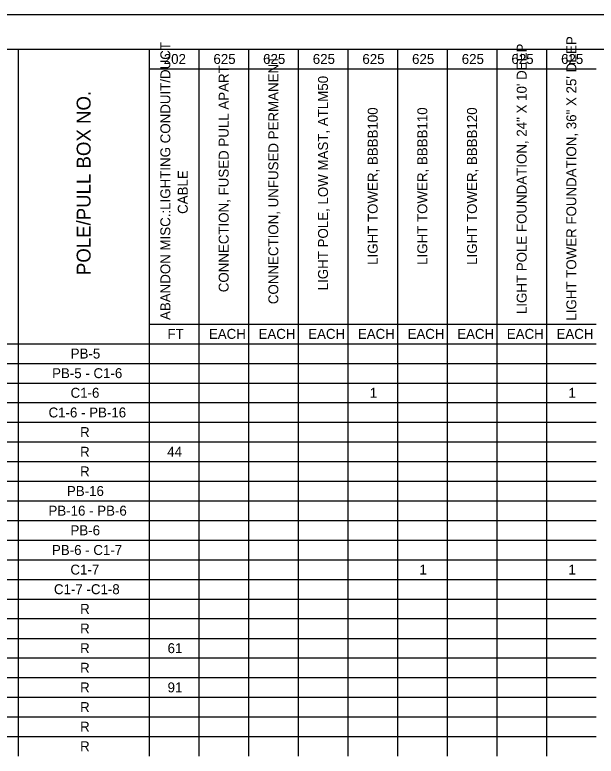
# Model space of a CAD drawing. Extents: x 0 to 34, y 0 to 22.
# Drawn here: x 8.35 to 16.82, y 11.19 to 22 of the extents above; entities that cross this region are included whole.
import ezdxf

# ---------------------------------------------------------------- set-up
doc = ezdxf.new("R2010")
doc.units = 0
for name, color, linetype in [('Default', 7, 'Continuous'), ('SH_Border', 7, 'Continuous'), ('SH_Cut_Line', 7, 'Continuous')]:
    doc.layers.add(name, color=color, linetype=linetype)

msp = doc.modelspace()

# ---------------------------------------------------------------- linework, layer by layer
at = {"layer": 'Default'}
for p, q in [((5.433, 21.5), (13.203, 21.5)), ((8.396, 21.5), (8.396, 21.214)), ((10.308, 21.5), (10.308, 21.214)), ((11.032, 21.5), (11.032, 21.214)), ((11.756, 21.5), (11.756, 21.214)), ((12.479, 21.5), (12.479, 21.214)), ((13.203, 21.5), (13.927, 21.5)), ((13.203, 21.5), (13.203, 21.214)), ((13.927, 21.5), (14.651, 21.5)), ((13.927, 21.5), (13.927, 21.214)), ((14.651, 21.5), (15.374, 21.5)), ((14.651, 21.5), (14.651, 21.214)), ((15.374, 21.5), (16.822, 21.5)), ((15.374, 21.5), (15.374, 21.214)), ((16.098, 21.5), (16.098, 21.214)), ((8.396, 21.214), (8.396, 20.927)), ((10.308, 21.214), (13.203, 21.214)), ((10.308, 21.214), (10.308, 20.927)), ((11.032, 21.214), (11.032, 20.927)), ((11.756, 21.214), (11.756, 20.927)), ((12.479, 21.214), (12.479, 20.927)), ((13.203, 21.214), (13.927, 21.214)), ((13.203, 21.214), (13.203, 20.927)), ((13.927, 21.214), (14.651, 21.214)), ((13.927, 21.214), (13.927, 20.927)), ((14.651, 21.214), (15.374, 21.214)), ((14.651, 21.214), (14.651, 20.927)), ((15.374, 21.214), (16.822, 21.214)), ((15.374, 21.214), (15.374, 20.927)), ((16.098, 21.214), (16.098, 20.927)), ((8.396, 20.927), (8.396, 20.641)), ((10.308, 20.927), (10.308, 20.641)), ((11.032, 20.927), (11.032, 20.641)), ((11.756, 20.927), (11.756, 20.641)), ((12.479, 20.927), (12.479, 20.641)), ((13.203, 20.927), (13.203, 20.641)), ((13.927, 20.927), (13.927, 20.641)), ((14.651, 20.927), (14.651, 20.641)), ((15.374, 20.927), (15.374, 20.641)), ((16.098, 20.927), (16.098, 20.641)), ((8.396, 20.641), (8.396, 20.354)), ((10.308, 20.641), (10.308, 20.354)), ((11.032, 20.641), (11.032, 20.354)), ((11.756, 20.641), (11.756, 20.354)), ((12.479, 20.641), (12.479, 20.354)), ((13.203, 20.641), (13.203, 20.354)), ((13.927, 20.641), (13.927, 20.354)), ((14.651, 20.641), (14.651, 20.354)), ((15.374, 20.641), (15.374, 20.354)), ((16.098, 20.641), (16.098, 20.354)), ((8.396, 20.354), (8.396, 20.068)), ((10.308, 20.354), (10.308, 20.068)), ((11.032, 20.354), (11.032, 20.068)), ((11.756, 20.354), (11.756, 20.068)), ((12.479, 20.354), (12.479, 20.068)), ((13.203, 20.354), (13.203, 20.068)), ((13.927, 20.354), (13.927, 20.068)), ((14.651, 20.354), (14.651, 20.068)), ((15.374, 20.354), (15.374, 20.068)), ((16.098, 20.354), (16.098, 20.068)), ((8.396, 20.068), (8.396, 19.782)), ((10.308, 20.068), (10.308, 19.782)), ((11.032, 20.068), (11.032, 19.782)), ((11.756, 20.068), (11.756, 19.782)), ((12.479, 20.068), (12.479, 19.782)), ((13.203, 20.068), (13.203, 19.782)), ((13.927, 20.068), (13.927, 19.782)), ((14.651, 20.068), (14.651, 19.782)), ((15.374, 20.068), (15.374, 19.782)), ((16.098, 20.068), (16.098, 19.782)), ((8.396, 19.782), (8.396, 19.495)), ((10.308, 19.782), (10.308, 19.495)), ((11.032, 19.782), (11.032, 19.495)), ((11.756, 19.782), (11.756, 19.495)), ((12.479, 19.782), (12.479, 19.495)), ((13.203, 19.782), (13.203, 19.495)), ((13.927, 19.782), (13.927, 19.495)), ((14.651, 19.782), (14.651, 19.495)), ((15.374, 19.782), (15.374, 19.495)), ((16.098, 19.782), (16.098, 19.495)), ((8.396, 19.495), (8.396, 19.209)), ((10.308, 19.495), (10.308, 19.209)), ((11.032, 19.495), (11.032, 19.209)), ((11.756, 19.495), (11.756, 19.209)), ((12.479, 19.495), (12.479, 19.209)), ((13.203, 19.495), (13.203, 19.209)), ((13.927, 19.495), (13.927, 19.209)), ((14.651, 19.495), (14.651, 19.209)), ((15.374, 19.495), (15.374, 19.209)), ((16.098, 19.495), (16.098, 19.209)), ((8.396, 19.209), (8.396, 18.922)), ((10.308, 19.209), (10.308, 18.922)), ((11.032, 19.209), (11.032, 18.922)), ((11.756, 19.209), (11.756, 18.922)), ((12.479, 19.209), (12.479, 18.922)), ((13.203, 19.209), (13.203, 18.922)), ((13.927, 19.209), (13.927, 18.922)), ((14.651, 19.209), (14.651, 18.922)), ((15.374, 19.209), (15.374, 18.922)), ((16.098, 19.209), (16.098, 18.922)), ((8.396, 18.922), (8.396, 18.636)), ((10.308, 18.922), (10.308, 18.636)), ((11.032, 18.922), (11.032, 18.636)), ((11.756, 18.922), (11.756, 18.636)), ((12.479, 18.922), (12.479, 18.636)), ((13.203, 18.922), (13.203, 18.636)), ((13.927, 18.922), (13.927, 18.636)), ((14.651, 18.922), (14.651, 18.636)), ((15.374, 18.922), (15.374, 18.636)), ((16.098, 18.922), (16.098, 18.636)), ((8.396, 18.636), (8.396, 18.35)), ((10.308, 18.636), (10.308, 18.35)), ((11.032, 18.636), (11.032, 18.35)), ((11.756, 18.636), (11.756, 18.35)), ((12.479, 18.636), (12.479, 18.35)), ((13.203, 18.636), (13.203, 18.35)), ((13.927, 18.636), (13.927, 18.35)), ((14.651, 18.636), (14.651, 18.35)), ((15.374, 18.636), (15.374, 18.35)), ((16.098, 18.636), (16.098, 18.35)), ((8.396, 18.35), (8.396, 18.063)), ((10.308, 18.35), (10.308, 18.063)), ((11.032, 18.35), (11.032, 18.063)), ((11.756, 18.35), (11.756, 18.063)), ((12.479, 18.35), (12.479, 18.063)), ((13.203, 18.35), (13.203, 18.063)), ((13.927, 18.35), (13.927, 18.063)), ((14.651, 18.35), (14.651, 18.063)), ((15.374, 18.35), (15.374, 18.063)), ((16.098, 18.35), (16.098, 18.063)), ((8.396, 18.063), (8.396, 17.777)), ((10.308, 18.063), (10.308, 17.777)), ((11.032, 18.063), (11.032, 17.777)), ((11.756, 18.063), (11.756, 17.777)), ((12.479, 18.063), (12.479, 17.777)), ((13.203, 18.063), (13.203, 17.777)), ((13.927, 18.063), (13.927, 17.777)), ((14.651, 18.063), (14.651, 17.777)), ((15.374, 18.063), (15.374, 17.777)), ((16.098, 18.063), (16.098, 17.777)), ((8.396, 17.777), (8.396, 17.49)), ((10.308, 17.777), (10.308, 17.49)), ((11.032, 17.777), (11.032, 17.49)), ((11.756, 17.777), (11.756, 17.49)), ((12.479, 17.777), (12.479, 17.49)), ((13.203, 17.777), (13.203, 17.49)), ((13.927, 17.777), (13.927, 17.49)), ((14.651, 17.777), (14.651, 17.49)), ((15.374, 17.777), (15.374, 17.49)), ((16.098, 17.777), (16.098, 17.49)), ((8.396, 17.49), (8.396, 17.204)), ((10.308, 17.49), (13.203, 17.49)), ((10.308, 17.49), (10.308, 17.204)), ((11.032, 17.49), (11.032, 17.204)), ((11.756, 17.49), (11.756, 17.204)), ((12.479, 17.49), (12.479, 17.204)), ((13.203, 17.49), (13.927, 17.49)), ((13.203, 17.49), (13.203, 17.204)), ((13.927, 17.49), (14.651, 17.49)), ((13.927, 17.49), (13.927, 17.204)), ((14.651, 17.49), (15.374, 17.49)), ((14.651, 17.49), (14.651, 17.204)), ((15.374, 17.49), (16.822, 17.49)), ((15.374, 17.49), (15.374, 17.204)), ((16.098, 17.49), (16.098, 17.204)), ((5.433, 17.204), (13.203, 17.204)), ((8.396, 17.204), (8.396, 16.918)), ((10.308, 17.204), (10.308, 16.918)), ((11.032, 17.204), (11.032, 16.918)), ((11.756, 17.204), (11.756, 16.918)), ((12.479, 17.204), (12.479, 16.918)), ((13.203, 17.204), (13.927, 17.204)), ((13.203, 17.204), (13.203, 16.918)), ((13.927, 17.204), (14.651, 17.204)), ((13.927, 17.204), (13.927, 16.918)), ((14.651, 17.204), (15.374, 17.204)), ((14.651, 17.204), (14.651, 16.918)), ((15.374, 17.204), (16.822, 17.204)), ((15.374, 17.204), (15.374, 16.918)), ((16.098, 17.204), (16.098, 16.918)), ((5.433, 16.918), (13.203, 16.918)), ((8.396, 16.918), (8.396, 16.631)), ((10.308, 16.918), (10.308, 16.631)), ((11.032, 16.918), (11.032, 16.631)), ((11.756, 16.918), (11.756, 16.631)), ((12.479, 16.918), (12.479, 16.631)), ((13.203, 16.918), (13.927, 16.918)), ((13.203, 16.918), (13.203, 16.631)), ((13.927, 16.918), (14.651, 16.918)), ((13.927, 16.918), (13.927, 16.631)), ((14.651, 16.918), (15.374, 16.918)), ((14.651, 16.918), (14.651, 16.631)), ((15.374, 16.918), (16.822, 16.918)), ((15.374, 16.918), (15.374, 16.631)), ((16.098, 16.918), (16.098, 16.631)), ((5.433, 16.631), (13.203, 16.631)), ((8.396, 16.631), (8.396, 16.345)), ((10.308, 16.631), (10.308, 16.345)), ((11.032, 16.631), (11.032, 16.345)), ((11.756, 16.631), (11.756, 16.345)), ((12.479, 16.631), (12.479, 16.345)), ((13.203, 16.631), (13.927, 16.631)), ((13.203, 16.631), (13.203, 16.345)), ((13.927, 16.631), (14.651, 16.631)), ((13.927, 16.631), (13.927, 16.345)), ((14.651, 16.631), (15.374, 16.631)), ((14.651, 16.631), (14.651, 16.345)), ((15.374, 16.631), (16.822, 16.631)), ((15.374, 16.631), (15.374, 16.345)), ((16.098, 16.631), (16.098, 16.345)), ((5.433, 16.345), (13.203, 16.345)), ((8.396, 16.345), (8.396, 16.058)), ((10.308, 16.345), (10.308, 16.058)), ((11.032, 16.345), (11.032, 16.058)), ((11.756, 16.345), (11.756, 16.058)), ((12.479, 16.345), (12.479, 16.058)), ((13.203, 16.345), (13.927, 16.345)), ((13.203, 16.345), (13.203, 16.058)), ((13.927, 16.345), (14.651, 16.345)), ((13.927, 16.345), (13.927, 16.058)), ((14.651, 16.345), (15.374, 16.345)), ((14.651, 16.345), (14.651, 16.058)), ((15.374, 16.345), (16.822, 16.345)), ((15.374, 16.345), (15.374, 16.058)), ((16.098, 16.345), (16.098, 16.058)), ((5.433, 16.058), (13.203, 16.058)), ((8.396, 16.058), (8.396, 15.772)), ((10.308, 16.058), (10.308, 15.772)), ((11.032, 16.058), (11.032, 15.772)), ((11.756, 16.058), (11.756, 15.772)), ((12.479, 16.058), (12.479, 15.772)), ((13.203, 16.058), (13.927, 16.058)), ((13.203, 16.058), (13.203, 15.772)), ((13.927, 16.058), (14.651, 16.058)), ((13.927, 16.058), (13.927, 15.772)), ((14.651, 16.058), (15.374, 16.058)), ((14.651, 16.058), (14.651, 15.772)), ((15.374, 16.058), (16.822, 16.058)), ((15.374, 16.058), (15.374, 15.772)), ((16.098, 16.058), (16.098, 15.772)), ((5.433, 15.772), (13.203, 15.772)), ((8.396, 15.772), (8.396, 15.486)), ((10.308, 15.772), (10.308, 15.486)), ((11.032, 15.772), (11.032, 15.486)), ((11.756, 15.772), (11.756, 15.486)), ((12.479, 15.772), (12.479, 15.486)), ((13.203, 15.772), (13.927, 15.772)), ((13.203, 15.772), (13.203, 15.486)), ((13.927, 15.772), (14.651, 15.772)), ((13.927, 15.772), (13.927, 15.486)), ((14.651, 15.772), (15.374, 15.772)), ((14.651, 15.772), (14.651, 15.486)), ((15.374, 15.772), (16.822, 15.772)), ((15.374, 15.772), (15.374, 15.486)), ((16.098, 15.772), (16.098, 15.486)), ((5.433, 15.486), (13.203, 15.486)), ((8.396, 15.486), (8.396, 15.199)), ((10.308, 15.486), (10.308, 15.199)), ((11.032, 15.486), (11.032, 15.199)), ((11.756, 15.486), (11.756, 15.199)), ((12.479, 15.486), (12.479, 15.199)), ((13.203, 15.486), (13.927, 15.486)), ((13.203, 15.486), (13.203, 15.199)), ((13.927, 15.486), (14.651, 15.486)), ((13.927, 15.486), (13.927, 15.199)), ((14.651, 15.486), (15.374, 15.486)), ((14.651, 15.486), (14.651, 15.199)), ((15.374, 15.486), (16.822, 15.486)), ((15.374, 15.486), (15.374, 15.199)), ((16.098, 15.486), (16.098, 15.199)), ((5.433, 15.199), (13.203, 15.199)), ((8.396, 15.199), (8.396, 14.913)), ((10.308, 15.199), (10.308, 14.913)), ((11.032, 15.199), (11.032, 14.913)), ((11.756, 15.199), (11.756, 14.913)), ((12.479, 15.199), (12.479, 14.913)), ((13.203, 15.199), (13.927, 15.199)), ((13.203, 15.199), (13.203, 14.913)), ((13.927, 15.199), (14.651, 15.199)), ((13.927, 15.199), (13.927, 14.913)), ((14.651, 15.199), (15.374, 15.199)), ((14.651, 15.199), (14.651, 14.913)), ((15.374, 15.199), (16.822, 15.199)), ((15.374, 15.199), (15.374, 14.913)), ((16.098, 15.199), (16.098, 14.913)), ((5.433, 14.913), (13.203, 14.913)), ((8.396, 14.913), (8.396, 14.626)), ((10.308, 14.913), (10.308, 14.626)), ((11.032, 14.913), (11.032, 14.626)), ((11.756, 14.913), (11.756, 14.626)), ((12.479, 14.913), (12.479, 14.626)), ((13.203, 14.913), (13.927, 14.913)), ((13.203, 14.913), (13.203, 14.626)), ((13.927, 14.913), (14.651, 14.913)), ((13.927, 14.913), (13.927, 14.626)), ((14.651, 14.913), (15.374, 14.913)), ((14.651, 14.913), (14.651, 14.626)), ((15.374, 14.913), (16.822, 14.913)), ((15.374, 14.913), (15.374, 14.626)), ((16.098, 14.913), (16.098, 14.626)), ((5.433, 14.626), (13.203, 14.626)), ((8.396, 14.626), (8.396, 14.34)), ((10.308, 14.626), (10.308, 14.34)), ((11.032, 14.626), (11.032, 14.34)), ((11.756, 14.626), (11.756, 14.34)), ((12.479, 14.626), (12.479, 14.34)), ((13.203, 14.626), (13.927, 14.626)), ((13.203, 14.626), (13.203, 14.34)), ((13.927, 14.626), (14.651, 14.626)), ((13.927, 14.626), (13.927, 14.34)), ((14.651, 14.626), (15.374, 14.626)), ((14.651, 14.626), (14.651, 14.34)), ((15.374, 14.626), (16.822, 14.626)), ((15.374, 14.626), (15.374, 14.34)), ((16.098, 14.626), (16.098, 14.34)), ((5.433, 14.34), (13.203, 14.34)), ((8.396, 14.34), (8.396, 14.054)), ((10.308, 14.34), (10.308, 14.054)), ((11.032, 14.34), (11.032, 14.054)), ((11.756, 14.34), (11.756, 14.054)), ((12.479, 14.34), (12.479, 14.054)), ((13.203, 14.34), (13.927, 14.34)), ((13.203, 14.34), (13.203, 14.054)), ((13.927, 14.34), (14.651, 14.34)), ((13.927, 14.34), (13.927, 14.054)), ((14.651, 14.34), (15.374, 14.34)), ((14.651, 14.34), (14.651, 14.054)), ((15.374, 14.34), (16.822, 14.34)), ((15.374, 14.34), (15.374, 14.054)), ((16.098, 14.34), (16.098, 14.054)), ((5.433, 14.054), (13.203, 14.054)), ((8.396, 14.054), (8.396, 13.767)), ((10.308, 14.054), (10.308, 13.767)), ((11.032, 14.054), (11.032, 13.767)), ((11.756, 14.054), (11.756, 13.767)), ((12.479, 14.054), (12.479, 13.767)), ((13.203, 14.054), (13.927, 14.054)), ((13.203, 14.054), (13.203, 13.767)), ((13.927, 14.054), (14.651, 14.054)), ((13.927, 14.054), (13.927, 13.767)), ((14.651, 14.054), (15.374, 14.054)), ((14.651, 14.054), (14.651, 13.767)), ((15.374, 14.054), (16.822, 14.054)), ((15.374, 14.054), (15.374, 13.767)), ((16.098, 14.054), (16.098, 13.767)), ((5.433, 13.767), (13.203, 13.767)), ((8.396, 13.767), (8.396, 13.481)), ((10.308, 13.767), (10.308, 13.481)), ((11.032, 13.767), (11.032, 13.481)), ((11.756, 13.767), (11.756, 13.481)), ((12.479, 13.767), (12.479, 13.481)), ((13.203, 13.767), (13.927, 13.767)), ((13.203, 13.767), (13.203, 13.481)), ((13.927, 13.767), (14.651, 13.767)), ((13.927, 13.767), (13.927, 13.481)), ((14.651, 13.767), (15.374, 13.767)), ((14.651, 13.767), (14.651, 13.481)), ((15.374, 13.767), (16.822, 13.767)), ((15.374, 13.767), (15.374, 13.481)), ((16.098, 13.767), (16.098, 13.481)), ((5.433, 13.481), (13.203, 13.481)), ((8.396, 13.481), (8.396, 13.195)), ((10.308, 13.481), (10.308, 13.195)), ((11.032, 13.481), (11.032, 13.195)), ((11.756, 13.481), (11.756, 13.195)), ((12.479, 13.481), (12.479, 13.195)), ((13.203, 13.481), (13.927, 13.481)), ((13.203, 13.481), (13.203, 13.195)), ((13.927, 13.481), (14.651, 13.481)), ((13.927, 13.481), (13.927, 13.195)), ((14.651, 13.481), (15.374, 13.481)), ((14.651, 13.481), (14.651, 13.195)), ((15.374, 13.481), (16.822, 13.481)), ((15.374, 13.481), (15.374, 13.195)), ((16.098, 13.481), (16.098, 13.195)), ((5.433, 13.195), (13.203, 13.195)), ((8.396, 13.195), (8.396, 12.908)), ((10.308, 13.195), (10.308, 12.908)), ((11.032, 13.195), (11.032, 12.908)), ((11.756, 13.195), (11.756, 12.908)), ((12.479, 13.195), (12.479, 12.908)), ((13.203, 13.195), (13.927, 13.195)), ((13.203, 13.195), (13.203, 12.908)), ((13.927, 13.195), (14.651, 13.195)), ((13.927, 13.195), (13.927, 12.908)), ((14.651, 13.195), (15.374, 13.195)), ((14.651, 13.195), (14.651, 12.908)), ((15.374, 13.195), (16.822, 13.195)), ((15.374, 13.195), (15.374, 12.908)), ((16.098, 13.195), (16.098, 12.908)), ((5.433, 12.908), (13.203, 12.908)), ((8.396, 12.908), (8.396, 12.622)), ((10.308, 12.908), (10.308, 12.622)), ((11.032, 12.908), (11.032, 12.622)), ((11.756, 12.908), (11.756, 12.622)), ((12.479, 12.908), (12.479, 12.622)), ((13.203, 12.908), (13.927, 12.908)), ((13.203, 12.908), (13.203, 12.622)), ((13.927, 12.908), (14.651, 12.908)), ((13.927, 12.908), (13.927, 12.622)), ((14.651, 12.908), (15.374, 12.908)), ((14.651, 12.908), (14.651, 12.622)), ((15.374, 12.908), (16.822, 12.908)), ((15.374, 12.908), (15.374, 12.622)), ((16.098, 12.908), (16.098, 12.622)), ((5.433, 12.622), (13.203, 12.622)), ((8.396, 12.622), (8.396, 12.335)), ((10.308, 12.622), (10.308, 12.335)), ((11.032, 12.622), (11.032, 12.335)), ((11.756, 12.622), (11.756, 12.335)), ((12.479, 12.622), (12.479, 12.335)), ((13.203, 12.622), (13.927, 12.622)), ((13.203, 12.622), (13.203, 12.335)), ((13.927, 12.622), (14.651, 12.622)), ((13.927, 12.622), (13.927, 12.335)), ((14.651, 12.622), (15.374, 12.622)), ((14.651, 12.622), (14.651, 12.335)), ((15.374, 12.622), (16.822, 12.622)), ((15.374, 12.622), (15.374, 12.335)), ((16.098, 12.622), (16.098, 12.335)), ((5.433, 12.335), (13.203, 12.335)), ((8.396, 12.335), (8.396, 12.049)), ((10.308, 12.335), (10.308, 12.049)), ((11.032, 12.335), (11.032, 12.049)), ((11.756, 12.335), (11.756, 12.049)), ((12.479, 12.335), (12.479, 12.049)), ((13.203, 12.335), (13.927, 12.335)), ((13.203, 12.335), (13.203, 12.049)), ((13.927, 12.335), (14.651, 12.335)), ((13.927, 12.335), (13.927, 12.049)), ((14.651, 12.335), (15.374, 12.335)), ((14.651, 12.335), (14.651, 12.049)), ((15.374, 12.335), (16.822, 12.335)), ((15.374, 12.335), (15.374, 12.049)), ((16.098, 12.335), (16.098, 12.049)), ((5.433, 12.049), (13.203, 12.049)), ((8.396, 12.049), (8.396, 11.763)), ((10.308, 12.049), (10.308, 11.763)), ((11.032, 12.049), (11.032, 11.763)), ((11.756, 12.049), (11.756, 11.763)), ((12.479, 12.049), (12.479, 11.763)), ((13.203, 12.049), (13.927, 12.049)), ((13.203, 12.049), (13.203, 11.763)), ((13.927, 12.049), (14.651, 12.049)), ((13.927, 12.049), (13.927, 11.763)), ((14.651, 12.049), (15.374, 12.049)), ((14.651, 12.049), (14.651, 11.763)), ((15.374, 12.049), (16.822, 12.049)), ((15.374, 12.049), (15.374, 11.763)), ((16.098, 12.049), (16.098, 11.763)), ((5.433, 11.763), (13.203, 11.763)), ((8.396, 11.763), (8.396, 11.476)), ((10.308, 11.763), (10.308, 11.476)), ((11.032, 11.763), (11.032, 11.476)), ((11.756, 11.763), (11.756, 11.476)), ((12.479, 11.763), (12.479, 11.476)), ((13.203, 11.763), (13.927, 11.763)), ((13.203, 11.763), (13.203, 11.476)), ((13.927, 11.763), (14.651, 11.763)), ((13.927, 11.763), (13.927, 11.476)), ((14.651, 11.763), (15.374, 11.763)), ((14.651, 11.763), (14.651, 11.476)), ((15.374, 11.763), (16.822, 11.763)), ((15.374, 11.763), (15.374, 11.476)), ((16.098, 11.763), (16.098, 11.476)), ((5.433, 11.476), (13.203, 11.476)), ((8.396, 11.476), (8.396, 11.19)), ((10.308, 11.476), (10.308, 11.19)), ((11.032, 11.476), (11.032, 11.19)), ((11.756, 11.476), (11.756, 11.19)), ((12.479, 11.476), (12.479, 11.19)), ((13.203, 11.476), (13.927, 11.476)), ((13.203, 11.476), (13.203, 11.19)), ((13.927, 11.476), (14.651, 11.476)), ((13.927, 11.476), (13.927, 11.19)), ((14.651, 11.476), (15.374, 11.476)), ((14.651, 11.476), (14.651, 11.19)), ((15.374, 11.476), (16.822, 11.476)), ((15.374, 11.476), (15.374, 11.19)), ((16.098, 11.476), (16.098, 11.19))]:
    msp.add_line(p, q, dxfattribs=at)
at = {"layer": 'SH_Border'}
msp.add_lwpolyline([(1.5, 21.5), (33.5, 21.5), (33.5, 0.5), (1.5, 0.5)], close=True, dxfattribs=at)
at = {"layer": 'SH_Cut_Line'}
msp.add_lwpolyline([(0, 0), (34, 0), (34, 22), (0, 22)], close=True, dxfattribs=at)

# ---------------------------------------------------------------- texts
at = {"layer": 'Default'}
for s, height, p in [('LIGHT TOWER FOUNDATION, 36" X 25\' DEEP', 0.14509, (16.533, 17.54)), ('ABANDON MISC.:LIGHTING CONDUIT/DUCT ', 0.14509, (10.616, 17.55)), ('LIGHT POLE FOUNDATION, 24" X 10\' DEEP', 0.14509, (15.809, 17.636)), ('CONNECTION, UNFUSED PERMANENT', 0.14509, (12.19, 17.781)), ('CONNECTION, FUSED PULL APART', 0.14509, (11.466, 17.955)), ('LIGHT POLE, LOW MAST, ATLM50', 0.14509, (12.914, 17.983)), ('POLE/PULL BOX NO.', 0.20313, (9.454, 18.204)), ('LIGHT TOWER, BBBB100', 0.14509, (13.638, 18.354)), ('LIGHT TOWER, BBBB110', 0.14509, (14.361, 18.354)), ('LIGHT TOWER, BBBB120', 0.14509, (15.085, 18.354)), ('CABLE', 0.1451, (10.87, 19.097))]:
    msp.add_text(s, height=height, rotation=90, dxfattribs=at).set_placement(p)
for s, height, p in [('202', 0.1449, (10.52, 21.284)), ('625', 0.1449, (11.244, 21.284)), ('625', 0.1449, (11.968, 21.284)), ('625', 0.1449, (12.692, 21.284)), ('625', 0.1449, (13.415, 21.284)), ('625', 0.1449, (14.139, 21.284)), ('625', 0.1449, (14.863, 21.284)), ('625', 0.1449, (15.587, 21.284)), ('625', 0.1449, (16.311, 21.284)), ('FT', 0.1449, (10.574, 17.275)), ('EACH', 0.1449, (11.178, 17.275)), ('EACH', 0.1449, (11.901, 17.275)), ('EACH', 0.1449, (12.625, 17.275)), ('EACH', 0.1449, (13.349, 17.275)), ('EACH', 0.1449, (14.073, 17.275)), ('EACH', 0.1449, (14.797, 17.275)), ('EACH', 0.1449, (15.52, 17.275)), ('EACH', 0.1449, (16.244, 17.275)), ('PB-5', 0.1449, (9.164, 16.988)), ('PB-5 - C1-6', 0.1449, (8.893, 16.702)), ('C1-6', 0.1449, (9.162, 16.416)), ('1', 0.145, (13.523, 16.416)), ('1', 0.145, (16.418, 16.416)), ('C1-6 - PB-16', 0.1449, (8.841, 16.129)), ('R', 0.145, (9.301, 15.843)), ('R', 0.145, (9.301, 15.556)), ('44', 0.1449, (10.57, 15.556)), ('R', 0.145, (9.301, 15.27)), ('PB-16', 0.1449, (9.109, 14.984)), ('PB-16 - PB-6', 0.1449, (8.84, 14.697)), ('PB-6', 0.1449, (9.161, 14.411)), ('PB-6 - C1-7', 0.1449, (8.891, 14.124)), ('C1-7', 0.1449, (9.16, 13.838)), ('1', 0.145, (14.247, 13.838)), ('1', 0.145, (16.418, 13.838)), ('C1-7 -C1-8', 0.1449, (8.92, 13.552)), ('R', 0.145, (9.301, 13.265)), ('R', 0.145, (9.301, 12.979)), ('R', 0.145, (9.301, 12.692)), ('61', 0.1449, (10.576, 12.692)), ('R', 0.145, (9.301, 12.406)), ('R', 0.145, (9.301, 12.12)), ('91', 0.1449, (10.576, 12.12)), ('R', 0.145, (9.301, 11.833)), ('R', 0.145, (9.301, 11.547)), ('R', 0.145, (9.301, 11.261))]:
    msp.add_text(s, height=height, dxfattribs=at).set_placement(p)

doc.saveas('drawing.dxf')
